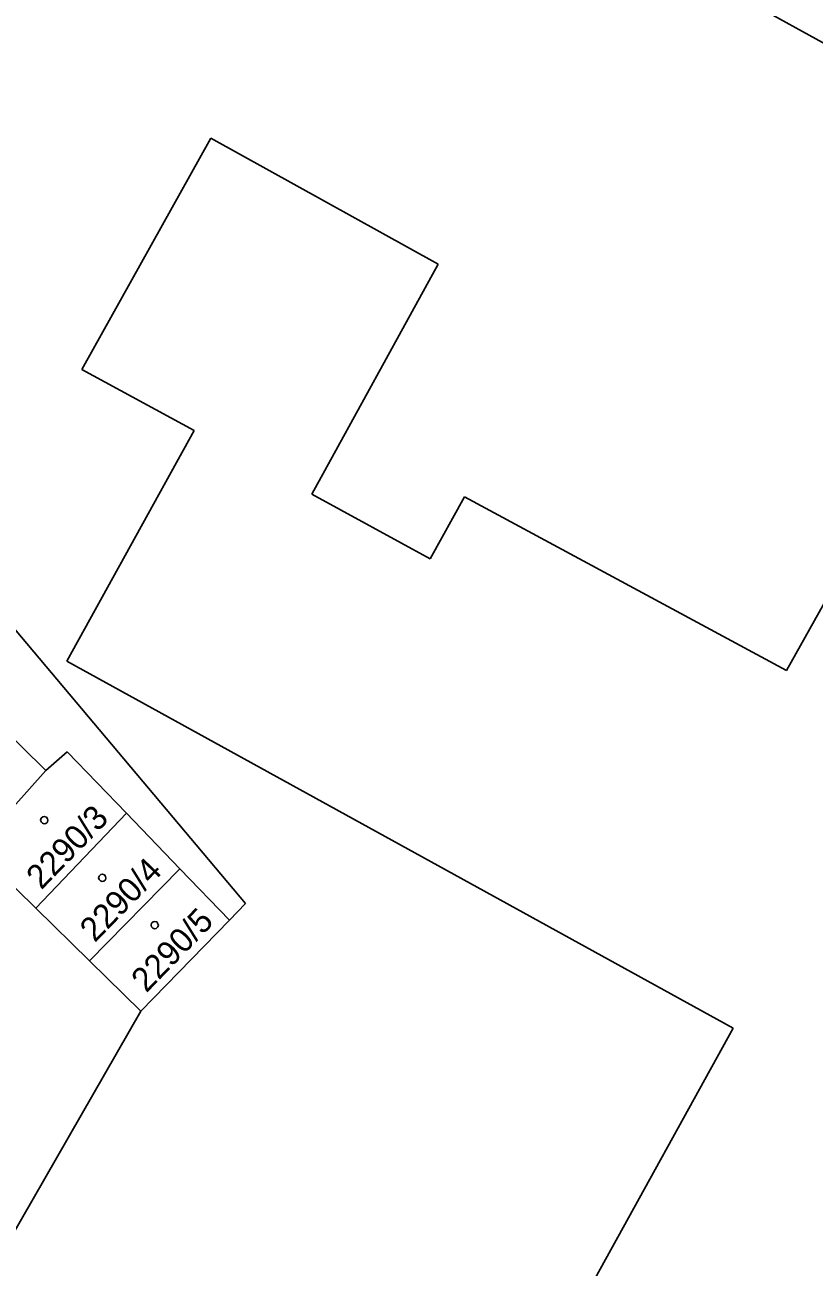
# Model space of a CAD drawing. Extents: x -528274 to -527531, y -1079304 to -1078580.
# Drawn here: x -527901.3 to -527864, y -1078912.6 to -1078853.9 of the extents above; entities that cross this region are included whole.
import ezdxf

# ---------------------------------------------------------------- set-up
doc = ezdxf.new("R2010")
doc.units = 0
doc.layers.add('katastrální mapa', color=7, linetype='Continuous')

msp = doc.modelspace()

# ---------------------------------------------------------------- linework, layer by layer
at = {"layer": 'katastrální mapa'}
for p, q in [((-527918.51, -1078824.42), (-527838.26, -1078868.7)), ((-527929.39, -1078849.6), (-527890.85, -1078895.43)), ((-527892.49, -1078859.25), (-527898.59, -1078870.19)), ((-527881.75, -1078865.21), (-527892.49, -1078859.25)), ((-527887.72, -1078876.08), (-527881.75, -1078865.21)), ((-527898.59, -1078870.19), (-527893.28, -1078873.07)), ((-527893.28, -1078873.07), (-527899.29, -1078883.97)), ((-527882.13, -1078879.13), (-527887.72, -1078876.08)), ((-527880.51, -1078876.2), (-527882.13, -1078879.13)), ((-527865.29, -1078884.42), (-527880.51, -1078876.2)), ((-527861.67, -1078877.91), (-527865.29, -1078884.42)), ((-527899.29, -1078883.97), (-527867.81, -1078901.32)), ((-527902.59, -1078886.88), (-527900.28, -1078889.14)), ((-527899.28, -1078888.26), (-527900.28, -1078889.14)), ((-527896.48, -1078891.16), (-527899.28, -1078888.26)), ((-527900.28, -1078889.14), (-527903.61, -1078892.85)), ((-527900.75, -1078895.65), (-527896.48, -1078891.16)), ((-527893.95, -1078893.79), (-527896.48, -1078891.16)), ((-527903.61, -1078892.85), (-527900.75, -1078895.65)), ((-527898.22, -1078898.14), (-527893.95, -1078893.79)), ((-527891.61, -1078896.22), (-527893.95, -1078893.79)), ((-527900.75, -1078895.65), (-527898.22, -1078898.14)), ((-527891.61, -1078896.22), (-527890.85, -1078895.43)), ((-527895.79, -1078900.52), (-527891.61, -1078896.22)), ((-527898.22, -1078898.14), (-527895.79, -1078900.52)), ((-527913.24, -1078930.89), (-527895.79, -1078900.52)), ((-527867.81, -1078901.32), (-527874.35, -1078913.18))]:
    msp.add_line(p, q, dxfattribs=at)
for points in [[(-527900.36, -1078891.32), (-527900.26, -1078891.34), (-527900.21, -1078891.43), (-527900.19, -1078891.49), (-527900.21, -1078891.58), (-527900.29, -1078891.65), (-527900.36, -1078891.66), (-527900.45, -1078891.63), (-527900.51, -1078891.57), (-527900.53, -1078891.49), (-527900.51, -1078891.4), (-527900.43, -1078891.33)], [(-527897.62, -1078894.05), (-527897.52, -1078894.07), (-527897.47, -1078894.16), (-527897.45, -1078894.22), (-527897.47, -1078894.31), (-527897.55, -1078894.38), (-527897.62, -1078894.39), (-527897.71, -1078894.36), (-527897.77, -1078894.3), (-527897.79, -1078894.22), (-527897.77, -1078894.13), (-527897.69, -1078894.06)], [(-527895.14, -1078896.28), (-527895.04, -1078896.3), (-527894.99, -1078896.39), (-527894.97, -1078896.45), (-527894.99, -1078896.54), (-527895.07, -1078896.61), (-527895.14, -1078896.62), (-527895.23, -1078896.59), (-527895.29, -1078896.53), (-527895.31, -1078896.45), (-527895.29, -1078896.36), (-527895.21, -1078896.29)]]:
    msp.add_lwpolyline(points, close=True, dxfattribs=at)

# ---------------------------------------------------------------- texts
for s, p in [('2290/3', (-527900.499, -1078894.816)), ('2290/4', (-527897.969, -1078897.306)), ('2290/5', (-527895.539, -1078899.686))]:
    msp.add_text(s, height=1.14, rotation=45.95122, dxfattribs=at).set_placement(p)

doc.saveas('drawing.dxf')
